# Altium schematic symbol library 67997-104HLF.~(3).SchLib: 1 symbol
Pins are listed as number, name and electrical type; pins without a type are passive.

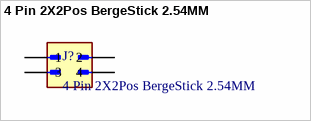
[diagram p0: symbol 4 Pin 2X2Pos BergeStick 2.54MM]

## 4 Pin 2X2Pos BergeStick 2.54MM
designator J?
4 Pin 2X2Pos THT BergeStick 2.54MM Amphenol 67997-104HLF; MF: Amphenol ICC
footprint AMPHENOL_67997-104HLF
pins: 1, 2, 3, 4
